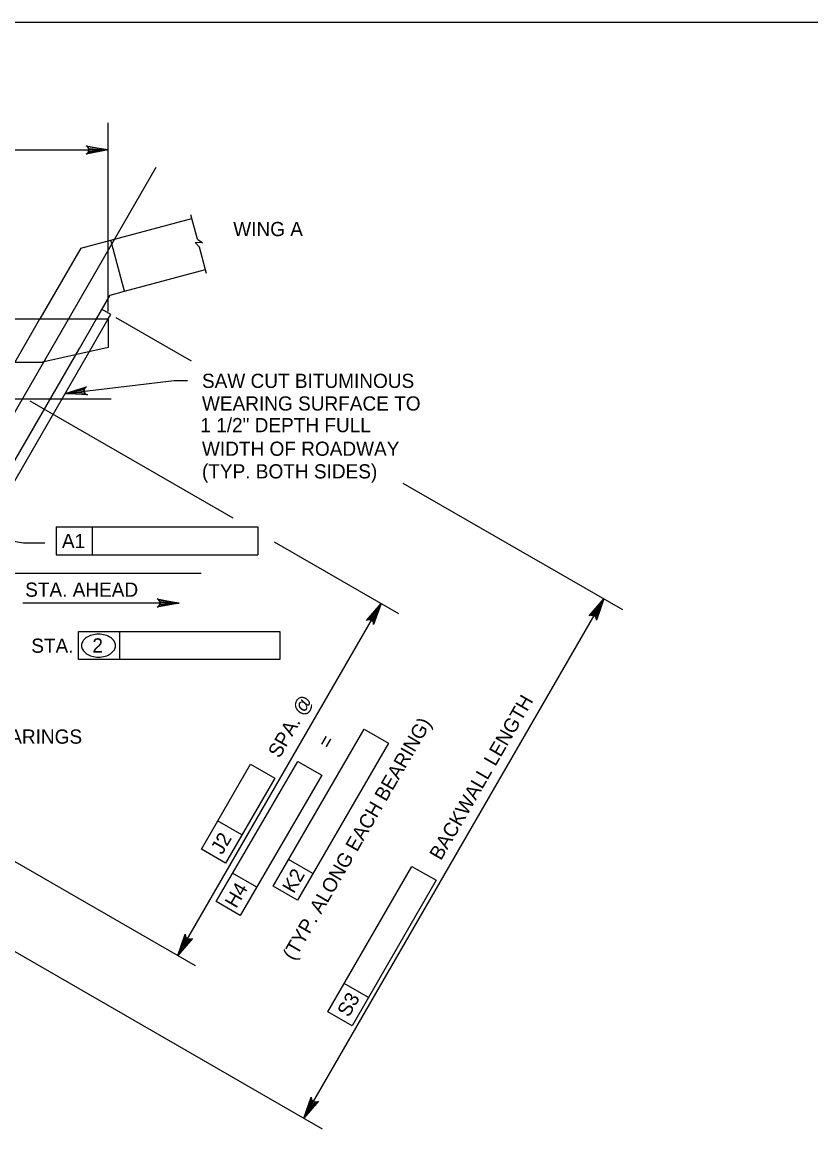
# Model space of a CAD drawing. Extents: x 638175 to 640495, y 294277 to 298435.
# Drawn here: x 638845 to 639011.5, y 295216.7 to 295450.5 of the extents above; entities that cross this region are included whole.
import ezdxf

# ---------------------------------------------------------------- set-up
doc = ezdxf.new("R2010")
doc.units = 0
for name, color, linetype in [('2', 7, 'Continuous'), ('3', 7, 'Continuous'), ('4', 7, 'Continuous')]:
    doc.layers.add(name, color=color, linetype=linetype)

msp = doc.modelspace()

# ---------------------------------------------------------------- linework, layer by layer
at = {"layer": '2'}
for p, q in [((638475.46, 295450.46), (639261.46, 295450.46)), ((638857.38, 295402.7), (638880.81, 295408.98)), ((638866.63, 295393.61), (638863.73, 295404.4)), ((638857.38, 295402.7), (638848.76, 295387.76)), ((638866.63, 295393.61), (638883.71, 295398.19)), ((638860.69, 295387.76), (638863.6, 295392.8)), ((638863.6, 295392.8), (638866.63, 295393.61)), ((638863.7, 295388.71), (638861.85, 295389.77)), ((638659.57, 295387.75), (638863.14, 295387.75)), ((638665, 295387.76), (638860.69, 295387.76)), ((638787.14, 295281.03), (638848.76, 295387.76)), ((638857.1, 295381.54), (638860.69, 295387.76)), ((638859.56, 295381.54), (638863.14, 295387.75)), ((638863.14, 295387.75), (638863.7, 295388.71)), ((638863.14, 295387.75), (638863.14, 295381.72)), ((638802.05, 295286.2), (638857.1, 295381.54)), ((638804.51, 295286.2), (638859.56, 295381.54)), ((638863.14, 295381.72), (638849.29, 295378.63)), ((638706.72, 295378.63), (638849.29, 295378.63))]:
    msp.add_line(p, q, dxfattribs=at)
at = {"layer": '3'}
for p, q in [((638881.98, 295404.62), (638880.61, 295409.74)), ((638883.03, 295403.84), (638881.54, 295403.92)), ((638881.54, 295403.92), (638882.43, 295402.95)), ((638881.98, 295404.62), (638883.03, 295403.84)), ((638883.93, 295397.35), (638882.43, 295402.95))]:
    msp.add_line(p, q, dxfattribs=at)
at = {"layer": '4'}
for p, q in [((638863.14, 295413.32), (638863.14, 295429.21)), ((638659.57, 295423.47), (638863.14, 295423.47)), ((638873.21, 295419.78), (638779.19, 295256.93)), ((638863.14, 295389.36), (638863.14, 295413.32)), ((638864.79, 295388.08), (638880.67, 295378.91)), ((638854.05, 295372), (638877.08, 295374.76)), ((638877.08, 295374.76), (638879.92, 295374.76)), ((638863.78, 295370.8), (638515.73, 295370.8)), ((638846.62, 295370.47), (638889.48, 295345.72)), ((638925.38, 295353.09), (638971.68, 295326.36)), ((638852.2, 295343.81), (638894.72, 295343.81)), ((638852.2, 295343.81), (638852.2, 295337.91)), ((638859.76, 295343.81), (638859.76, 295337.91)), ((638894.72, 295343.81), (638894.72, 295337.91)), ((638839.13, 295341.47), (638845.27, 295340.44)), ((638845.27, 295340.44), (638849.75, 295340.44)), ((638898.22, 295340.67), (638924.45, 295325.53)), ((638852.2, 295337.91), (638894.72, 295337.91)), ((638882.76, 295333.98), (638590.47, 295333.98)), ((638904.45, 295218.91), (638967.78, 295328.61)), ((638878.16, 295327.73), (638845.12, 295327.73)), ((638877.84, 295253.31), (638920.77, 295327.66)), ((638877.84, 295253.3), (638920.77, 295327.66)), ((638856.88, 295315.81), (638856.88, 295321.71)), ((638856.88, 295321.71), (638899.4, 295321.71)), ((638865.63, 295315.81), (638865.63, 295321.71)), ((638899.4, 295321.71), (638899.4, 295315.81)), ((638899.4, 295315.81), (638856.88, 295315.81)), ((638897.96, 295267.93), (638917.2, 295301.12)), ((638917.2, 295301.12), (638922.31, 295298.17)), ((638803.69, 295296.11), (638881.52, 295251.18)), ((638922.31, 295298.17), (638903.08, 295264.98)), ((638882.82, 295275.76), (638893.18, 295293.71)), ((638885.93, 295264.69), (638903.15, 295294.3)), ((638893.18, 295293.71), (638898.3, 295290.76)), ((638903.15, 295294.3), (638908.27, 295291.35)), ((638908.27, 295291.35), (638891.04, 295261.74)), ((638898.3, 295290.76), (638887.93, 295272.81)), ((638891.38, 295278.78), (638886.26, 295281.73)), ((638801.71, 295278.23), (638908.35, 295216.66)), ((638887.93, 295272.81), (638882.82, 295275.76)), ((638906.34, 295270.63), (638901.23, 295273.59)), ((638894.51, 295267.7), (638889.4, 295270.67)), ((638909.52, 295241.41), (638927.26, 295272.12)), ((638927.26, 295272.12), (638932.37, 295269.17)), ((638903.08, 295264.98), (638897.96, 295267.93)), ((638932.37, 295269.17), (638914.64, 295238.46)), ((638891.04, 295261.74), (638885.93, 295264.69)), ((638918.08, 295244.42), (638912.97, 295247.37)), ((638914.64, 295238.46), (638909.52, 295241.41))]:
    msp.add_line(p, q, dxfattribs=at)
for points in [[(638863.14, 295423.47), (638858.48, 295422.6), (638858.84, 295422.85), (638859.03, 295423.16), (638859.08, 295423.47), (638859.03, 295423.79), (638858.84, 295424.1), (638858.48, 295424.35), (638863.14, 295423.47), (638858.84, 295424.1), (638859.03, 295423.79), (638863.14, 295423.47), (638859.08, 295423.47), (638859.03, 295423.16), (638863.14, 295423.47), (638858.84, 295422.85)], [(638854.05, 295372), (638858.57, 295373.42), (638858.24, 295373.13), (638858.1, 295372.8), (638858.08, 295372.48), (638858.17, 295372.18), (638858.39, 295371.89), (638858.78, 295371.69), (638854.05, 295372), (638858.39, 295371.89), (638858.17, 295372.18), (638854.05, 295372), (638858.08, 295372.48), (638858.1, 295372.8), (638854.05, 295372), (638858.24, 295373.13)], [(638878.16, 295327.73), (638873.5, 295326.86), (638873.86, 295327.11), (638874.05, 295327.42), (638874.1, 295327.73), (638874.05, 295328.05), (638873.86, 295328.36), (638873.5, 295328.61), (638878.16, 295327.73), (638873.86, 295328.36), (638874.05, 295328.05), (638878.16, 295327.73), (638874.1, 295327.73), (638874.05, 295327.42), (638878.16, 295327.73), (638873.86, 295327.11)], [(638967.78, 295328.61), (638966.21, 295324.14), (638966.18, 295324.57), (638966, 295324.89), (638965.75, 295325.09), (638965.46, 295325.2), (638965.09, 295325.2), (638964.7, 295325.01), (638967.78, 295328.61), (638965.09, 295325.2), (638965.46, 295325.2), (638967.78, 295328.61), (638965.75, 295325.09), (638966, 295324.89), (638967.78, 295328.61), (638966.18, 295324.57)], [(638920.77, 295327.66), (638919.19, 295323.18), (638919.16, 295323.62), (638918.98, 295323.94), (638918.73, 295324.14), (638918.44, 295324.25), (638918.07, 295324.25), (638917.68, 295324.06), (638920.77, 295327.66), (638918.07, 295324.25), (638918.44, 295324.25), (638920.77, 295327.66), (638918.73, 295324.14), (638918.98, 295323.94), (638920.77, 295327.66), (638919.16, 295323.62)], [(638877.84, 295253.31), (638879.41, 295257.78), (638879.45, 295257.34), (638879.62, 295257.03), (638879.87, 295256.82), (638880.17, 295256.71), (638880.53, 295256.72), (638880.92, 295256.91), (638877.84, 295253.31), (638880.53, 295256.72), (638880.17, 295256.71), (638877.84, 295253.31), (638879.87, 295256.82), (638879.62, 295257.03), (638877.84, 295253.31), (638879.45, 295257.34)], [(638904.45, 295218.91), (638906.02, 295223.39), (638906.06, 295222.95), (638906.24, 295222.63), (638906.48, 295222.43), (638906.78, 295222.32), (638907.14, 295222.33), (638907.54, 295222.51), (638904.45, 295218.91), (638907.14, 295222.33), (638906.78, 295222.32), (638904.45, 295218.91), (638906.48, 295222.43), (638906.24, 295222.63), (638904.45, 295218.91), (638906.06, 295222.95)]]:
    msp.add_lwpolyline(points, dxfattribs=at)
for points in [[(638965.85, 295326.26), (638966.72, 295325.76), (638967.78, 295328.61)], [(638918.94, 295325.44), (638919.76, 295324.97), (638920.77, 295327.66)], [(638878.85, 295256), (638879.66, 295255.52), (638877.84, 295253.3)]]:
    msp.add_lwpolyline(points, close=True, dxfattribs=at)
for centre, radius, start, end in [((638859.21, 295318.75), 1.68, 148.5507, 180), ((638860.12, 295318.19), 2.75, 124.109, 148.5507), ((638860.72, 295317.3), 3.82, 105.6708, 124.109), ((638861.12, 295315.9), 5.27, 90, 105.6708), ((638861.12, 295315.9), 5.27, 74.3292, 90), ((638861.51, 295317.3), 3.82, 55.891, 74.3292), ((638862.11, 295318.19), 2.75, 31.4493, 55.891), ((638863.02, 295318.75), 1.68, 0, 31.4493), ((638859.21, 295318.75), 1.68, 180, 211.4493), ((638860.12, 295319.31), 2.75, 211.4493, 235.891), ((638860.72, 295320.19), 3.82, 235.891, 254.3292), ((638861.51, 295320.19), 3.82, 285.6708, 304.109), ((638862.11, 295319.31), 2.75, 304.109, 328.5507), ((638863.02, 295318.75), 1.68, 328.5507, 0), ((638861.12, 295321.59), 5.27, 254.3292, 270), ((638861.12, 295321.59), 5.27, 270, 285.6708)]:
    msp.add_arc(centre, radius, start, end, dxfattribs=at)

# ---------------------------------------------------------------- texts
for s, p in [('WING A', (638889.55, 295405.25)), ('SAW CUT BITUMINOUS', (638882.95, 295373.18)), ('WEARING SURFACE TO', (638882.95, 295368.4)), ('1 1/2" DEPTH FULL', (638882.61, 295363.83)), ('WIDTH OF ROADWAY', (638882.95, 295358.84)), ('(TYP. BOTH SIDES)', (638882.95, 295354.06)), ('STA. AHEAD', (638845.63, 295329.07)), ('STA.', (638846.92, 295317.23)), ('2', (638859.82, 295317.29)), ('C BEARINGS', (638832.91, 295298.03))]:
    msp.add_text(s, height=3, dxfattribs=at).set_placement(p)
for s, rotation, p in [('A1', 359.9382, (638853.39, 295339.36)), ('SPA. @', 60, (638899.31, 295294.79)), ('BACKWALL LENGTH', 60, (638933.38, 295273.2)), ('(TYP. ALONG EACH BEARING)', 60, (638902.4, 295252.04)), ('= ', 60, (638909.83, 295296.75)), ('J2', 60, (638887.22, 295274.44)), ('K2', 60, (638902.34, 295266.22)), ('H4', 59.8092, (638890.18, 295263.09)), ('S3', 60, (638913.92, 295240.07))]:
    msp.add_text(s, height=3, rotation=rotation, dxfattribs=at).set_placement(p)

doc.saveas('drawing.dxf')
